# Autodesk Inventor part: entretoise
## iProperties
Created: 2009-03
Part Number: entretoise
Document SubType Name: Modeling
Designer: Ordi1
Author: Ordi1
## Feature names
1. Extrusion1
2. Chanfrein1 [Chamfer]
